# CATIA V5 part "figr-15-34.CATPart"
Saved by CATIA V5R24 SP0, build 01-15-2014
Part number: Part1
Bounding box of the stored display mesh (mm): x -40.264 to 42.014, y -25.445 to 25.445, z -51 to 0.75
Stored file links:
  D:\KAVITA\CATIA V5-6R2014 Project_ Kavita\CATIA V5-6R2014_partfiles\Partfiles\c15_catia_v5-6r2014_prt\figr-15-34.CATPart
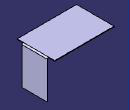
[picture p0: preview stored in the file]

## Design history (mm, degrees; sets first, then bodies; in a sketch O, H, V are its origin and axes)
SheetMetalParameters1: Thickness 0.75, BendRadius 1, KFactor 0.356492 {= log(min(100,max(20*SheetMetalParameters1.BendRadius,SheetMetalParameters1.Thickness)/SheetMetalParameters1.Thickness))/log(100)/2}, ReliefRadialLength 1, ReliefAxialLength 2, MinimumBendRadius 0
Body1 (main body)
  Sketch1 on xy-plane, origin (0, 0, 0), H (1, 0, 0), V (0, 1, 0)
    line L1 (-40.2643, 25.445) -> (40.2643, 25.445)
    line L2 (40.2643, 25.445) -> (40.2643, -25.445)
    line L3 (40.2643, -25.445) -> (-40.2643, -25.445)
    line L4 (-40.2643, -25.445) -> (-40.2643, 25.445)
    horizontal: L1 H, L3 H
    vertical: L2 V, L4 V
    symmetry: L1 L3 H, L4 L2 V
  Wall1: Thickness 0.75, Profile Sketch1
  Plane1: type Offset, RefPlane zx-plane, Offset 17
  Plane2: type Offset, RefPlane zx-plane, Offset 17, reversed
  Flange1: Angle 90, Length 50, Radius 1, KFacteur 0.356492 {= log(min(100,max(20*Flange1.Radius,SheetMetalParameters1.Thickness)/SheetMetalParameters1.Thickness))/log(100)/2}, Guide edge [face of Wall1 | face of Wall1], Limit1 Plane1, Limit2 Plane2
